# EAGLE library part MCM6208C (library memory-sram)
MEMORY
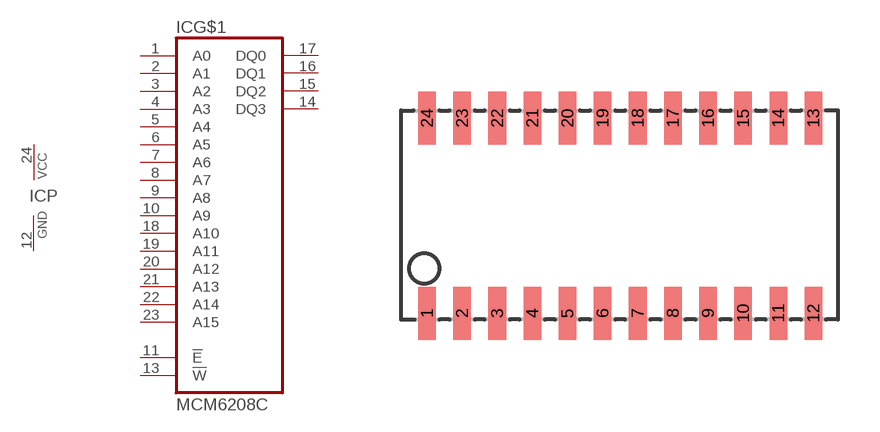
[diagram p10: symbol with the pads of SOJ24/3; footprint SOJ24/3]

Designator prefix IC; gates G$1=CM6208C P=PWRN

## MCM6208C  [SOJ24/3]
1  G$1:A0  in
2  G$1:A1  in
3  G$1:A2  in
4  G$1:A3  in
5  G$1:A4  in
6  G$1:A5  in
7  G$1:A6  in
8  G$1:A7  in
9  G$1:A8  in
10  G$1:A9  in
11  G$1:!E  in
12  P:GND  pwr
13  G$1:!W  in
14  G$1:DQ3
15  G$1:DQ2
16  G$1:DQ1
17  G$1:DQ0
18  G$1:A10  in
19  G$1:A11  in
20  G$1:A12  in
21  G$1:A13  in
22  G$1:A14  in
23  G$1:A15  in
24  P:VCC  pwr

## Footprint SOJ24/3 (pad centres in mm)
Small Outline J-Bend
smd 0.635 x 1.905: 1 -6.35,-3.531; 2 -5.08,-3.531; 3 -3.81,-3.531; 4 -2.54,-3.531; 5 -1.27,-3.531; 6 0,-3.531; 7 1.27,-3.531; 8 2.54,-3.531; 9 3.81,-3.531; 10 5.08,-3.531; 11 6.35,-3.531; 12 7.62,-3.531; 13 7.62,3.531; 14 6.35,3.531; 15 5.08,3.531; 16 3.81,3.531; 17 2.54,3.531; 18 1.27,3.531; 19 0,3.531; 20 -1.27,3.531; 21 -2.54,3.531; 22 -3.81,3.531; 23 -5.08,3.531; 24 -6.35,3.531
